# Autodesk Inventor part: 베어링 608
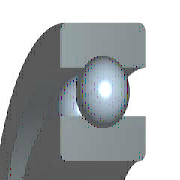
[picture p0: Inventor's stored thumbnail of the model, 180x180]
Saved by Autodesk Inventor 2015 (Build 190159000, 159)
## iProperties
IsCustomPart: 1
Created: 2012-02
Part Number: 베어링 608
Material: 강철, 연강
Description: 깊은 그루브 볼 베어링
Document SubType Name: Modeling
Standard: KS B 2023
Designer: mduedu
Standards Organization: KS
Language: ko-KR
Size Designation: 608 - 8 x 22 x 7
Categories: <MemberInstance><Categories><Category DisplayName="샤프트 부품" InternalName="7f7aeb1f-a693-4053-b835-cee3144e0d98" Mnemonic="SHFT"><Category DisplayName="베어링" Inter
Density: 1 g/cm^3
Appearance: Steel
Author: mduedu
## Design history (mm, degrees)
sketch "스케치" dims "d0" = 3.64 (= -0.26 x WD + 0.26 x BD)
  geometry: L1 (1.68, 7.5)-(5.32, 7.5); L2 (3.5, 7.5)-(3.5, 5.68); L3 (3.5, 7.5)-(3.5, 9.32); L4 (2.148, 6.282)-(0, 6.282); L5 (0, 4)-(7, 4); L6 (2.148, 8.718)-(0, 8.718); L7 (0, 11)-(7, 11); L8 (7, 4)-(7, 6.282); L9 (4.852, 6.282)-(7, 6.282); L10 (4.852, 8.718)-(7, 8.718); L11 (7, 11)-(7, 8.718); L12 (-1.4, 0)-(8.4, 0) reference; L13 (0, -0.3)-(0, 5.3) reference
  constraints: 22 end point, 4 point on line, 2 collinear, 2 perpendicular, 2 symmetric about line, 1 midpoint, 1 parallel, 14 other
  dimensions: "d9" = 8 diameter of L5 L12 (= WD); "d11" = 22 diameter of L7 L12 (= BD); "d12" = 7 distance between parallel lines of L8 L13 (= KB); "d13" = 12.564 diameter of L9 L12 (= 0.326 x BD + 0.674 x WD)
revolve "본체" stored, may be unused: angle "d6" = 90 deg
revolve "볼" stored, may be unused: angle "d7" = 90 deg
pattern_circular "IDS_ARRAYBALL[SIMPL:T]" dims angle "d3" = 360 deg
body "Solid1"
fillet "모깎기1" dims "d1" = 0.3 (= KRS)
other parameters: "WD" = 8 [user parameter; used in 5 equation terms], "BD" = 22 [user parameter; used in 5 equation terms], "KB" = 7 [user parameter; used in 1 equation term], "KRS" = 0.3 [user parameter; used in 1 equation term], "d4" = 0, "d5" = 0, "d8" = 0, "d14" = 0, "d15" = 0, "BBA" = 0 [user parameter], "BC0" = 1370000 [user parameter], "BC" = 3250000 [user parameter], "BR" = 11 (= 0.5 x BD) [user parameter], "WR" = 4 (= 0.5 x WD) [user parameter]
